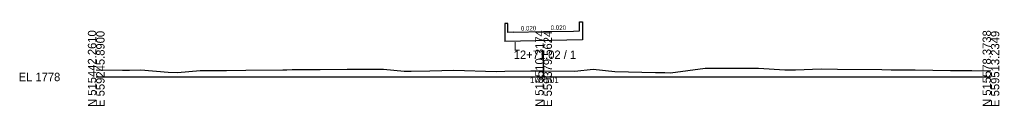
# Model space of a CAD drawing. Extents: x -26 to 1303, y -10 to 9545.
# Drawn here: x -25.7 to 302.8, y 6990.3 to 7018.4 of the extents above; entities that cross this region are included whole.
import ezdxf

# ---------------------------------------------------------------- set-up
doc = ezdxf.new("R2010")
doc.units = 0
for name, color, linetype in [('Exist Cross Section Cell', 7, 'Continuous'), ('Exist XS Center Line Elevation Label', 7, 'Continuous'), ('Exist XS Ground Line', 7, 'Continuous'), ('Prop XS Bridge', 7, 'Continuous'), ('Prop XS Dump Level', 7, 'Continuous'), ('Prop XS SE Text', 7, 'Continuous')]:
    doc.layers.add(name, color=color, linetype=linetype)

msp = doc.modelspace()

# ---------------------------------------------------------------- linework, layer by layer
at = {"layer": 'Exist Cross Section Cell'}
for p, q in [((150, 7000), (150, 7008.82)), ((0, 7000), (150, 7000)), ((150, 7000), (300, 7000))]:
    msp.add_line(p, q, dxfattribs=at)
at = {"layer": 'Exist XS Ground Line'}
for p, q in [((0, 7002.38), (8.79, 7002.22)), ((8.79, 7002.22), (11.18, 7002.25)), ((11.18, 7002.25), (14.98, 7002.35)), ((14.98, 7002.35), (24.17, 7001.6)), ((24.17, 7001.6), (27.21, 7001.52)), ((27.21, 7001.52), (34.9, 7002.17)), ((34.9, 7002.17), (43.72, 7002.19)), ((43.72, 7002.19), (50.22, 7002.27)), ((50.22, 7002.27), (62.57, 7002.42)), ((62.57, 7002.42), (63.87, 7002.35)), ((63.87, 7002.35), (65.75, 7002.46)), ((65.75, 7002.46), (75.08, 7002.52)), ((75.08, 7002.52), (84.16, 7002.56)), ((84.16, 7002.56), (92.75, 7002.6)), ((92.75, 7002.6), (96.27, 7002.59)), ((96.27, 7002.59), (103.31, 7001.93)), ((103.31, 7001.93), (105.63, 7001.97)), ((105.63, 7001.97), (111.86, 7002.09)), ((111.86, 7002.09), (119.95, 7002.25)), ((119.95, 7002.25), (134.05, 7001.88)), ((134.05, 7001.88), (137.03, 7001.96)), ((137.03, 7001.96), (145.74, 7002.02)), ((145.74, 7002.02), (150, 7002.01)), ((150, 7002.01), (160.48, 7001.99)), ((160.48, 7001.99), (166.65, 7002.56)), ((166.65, 7002.56), (173.92, 7001.86)), ((173.92, 7001.86), (187.5, 7001.5)), ((187.5, 7001.5), (188.99, 7001.47)), ((188.99, 7001.47), (190.63, 7001.45)), ((190.63, 7001.45), (192.58, 7001.42)), ((192.58, 7001.42), (204.22, 7002.94)), ((204.22, 7002.94), (208.14, 7002.89)), ((208.14, 7002.89), (212.83, 7002.93)), ((212.83, 7002.93), (215.09, 7002.9)), ((215.09, 7002.9), (222.03, 7002.91)), ((222.03, 7002.91), (230.89, 7002.41)), ((230.89, 7002.41), (232.49, 7002.4)), ((232.49, 7002.4), (234.52, 7002.39)), ((234.52, 7002.39), (243.12, 7002.7)), ((243.12, 7002.7), (248.57, 7002.65)), ((248.57, 7002.65), (263.45, 7002.45)), ((263.45, 7002.45), (266.56, 7002.43)), ((266.56, 7002.43), (274.54, 7002.38)), ((274.54, 7002.38), (286.42, 7002.19)), ((286.42, 7002.19), (293.54, 7002.14)), ((293.54, 7002.14), (300, 7002.09))]:
    msp.add_line(p, q, dxfattribs=at)
at = {"layer": 'Prop XS Bridge'}
for p, q in [((137, 7017.88), (137, 7014.88)), ((138, 7017.88), (137, 7017.88)), ((138, 7014.88), (138, 7017.88)), ((162, 7015.36), (162, 7018.36)), ((162, 7018.36), (163, 7018.36)), ((163, 7018.36), (163, 7015.36)), ((137, 7014.88), (137, 7011.88)), ((140, 7014.92), (138, 7014.88)), ((140, 7014.92), (150, 7015.12)), ((150, 7015.12), (160, 7015.32)), ((160, 7015.32), (162, 7015.36)), ((163, 7015.36), (163, 7012.36)), ((163, 7012.36), (137, 7011.88))]:
    msp.add_line(p, q, dxfattribs=at)
at = {"layer": 'Prop XS Dump Level'}
for p, q in [((140, 7014.92), (150, 7015.12)), ((150, 7015.12), (160, 7015.32))]:
    msp.add_line(p, q, dxfattribs=at)

# ---------------------------------------------------------------- texts
at = {"layer": 'Exist Cross Section Cell'}
for s, p in [('N 515442.2610', (0, 6990)), ('E 559245.8900', (2.8, 6990)), ('N 515510.3174', (150, 6990)), ('E 559379.5624', (152.8, 6990)), ('N 515578.3738', (300, 6990)), ('E 559513.2349', (302.8, 6990))]:
    msp.add_text(s, height=2.8, rotation=90, dxfattribs=at).set_placement(p)
for s, p in [('L', (140, 7008.82)), ('12+71.02 / 1', (140, 7006.02)), ('EL 1778', (-26, 6998.6))]:
    msp.add_text(s, height=2.8, dxfattribs=at).set_placement(p)
at = {"layer": 'Exist XS Center Line Elevation Label'}
msp.add_text('1780.01', height=2, dxfattribs=at).set_placement((145.43, 6998.01))
at = {"layer": 'Prop XS SE Text'}
for p in [(142.38, 7015.46), (152.38, 7015.66)]:
    msp.add_text('0.020', height=1.5, rotation=1.1458, dxfattribs=at).set_placement(p)

doc.saveas('drawing.dxf')
